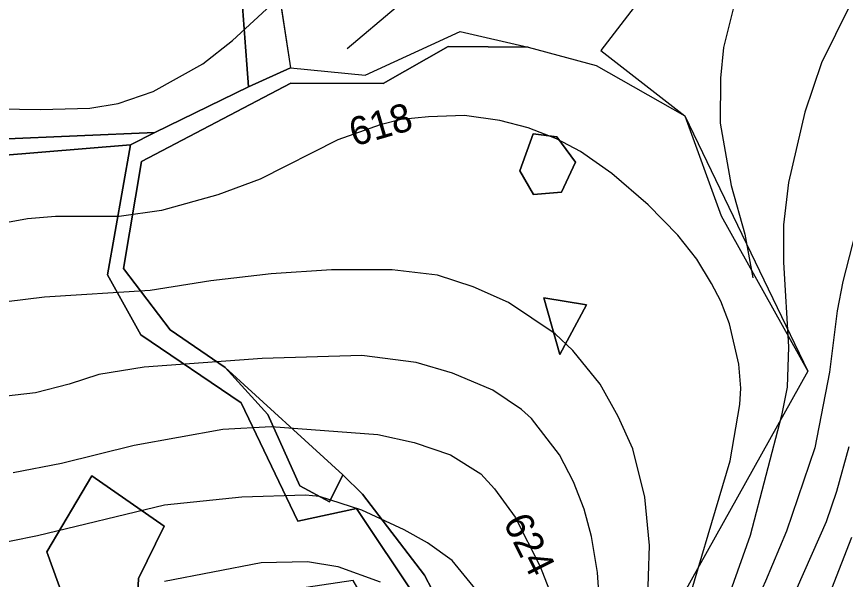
# Model space of a CAD drawing. Extents: x -709418 to -703832, y -1161719 to -1157826.
# Drawn here: x -705715.8 to -705481.3, y -1160126.6 to -1159967.4 of the extents above; entities that cross this region are included whole.
import ezdxf

# ---------------------------------------------------------------- set-up
doc = ezdxf.new("R2010")
doc.units = 0
for name, color, linetype in [('102_obvod PÚ', 7, 'Continuous'), ('120_vrstevnice hlavní', 7, 'Continuous'), ('121_vrstevnice hlavní_popis', 7, 'Continuous'), ('122_vrstevnice základní', 7, 'Continuous'), ('124_vrstevnice doplňková', 7, 'Continuous'), ('206_TTP_KN', 7, 'Continuous'), ('210_ostatní plocha_KN', 7, 'Continuous'), ('609_LBC_stav', 7, 'Continuous')]:
    doc.layers.add(name, color=color, linetype=linetype)

msp = doc.modelspace()

# ---------------------------------------------------------------- linework, layer by layer
at = {"layer": '102_obvod PÚ'}
msp.add_lwpolyline([(-705648.46, -1159916.07), (-705638.24, -1159981.92), (-705617.18, -1159983.99), (-705590.25, -1159971.69), (-705571.02, -1159976.06), (-705551.84, -1159981.31), (-705526.72, -1159995.51), (-705516.48, -1160023.76), (-705491.92, -1160067.67), (-705561.96, -1160193.15), (-705563.65, -1160193.42), (-705572.14, -1160189.71), (-705572.57, -1160180.72), (-705578.63, -1160182.19), (-705583.87, -1160190.33), (-705620.59, -1160126.86), (-705658.56, -1160132.55), (-705655.72, -1160146.23), (-705653.33, -1160157.69), (-705696.03, -1160165.25), (-705691.55, -1160200.19), (-705733.28, -1160203.04)], dxfattribs=at)
at = {"layer": '120_vrstevnice hlavní'}
for points in [[(-705537.29, -1160134.37), (-705536.72, -1160116.99), (-705538.01, -1160103.31), (-705541.43, -1160089.63), (-705545.56, -1160080.51), (-705550.69, -1160071.39), (-705558.38, -1160061.84), (-705563.37, -1160057.14), (-705576.62, -1160048.31), (-705586.6, -1160043.89), (-705596.71, -1160040.61), (-705609.54, -1160039.04), (-705626.64, -1160039.04), (-705643.74, -1160040.18), (-705660.84, -1160042.18), (-705677.93, -1160044.89), (-705707.86, -1160046.74), (-705744.84, -1160051.31)], [(-705479.58, -1160114.71), (-705485.28, -1160129.24), (-705497.54, -1160153.47), (-705506.23, -1160168), (-705512.93, -1160182.54), (-705513.35, -1160187.38), (-705513.22, -1160190.87), (-705511.93, -1160194.22), (-705508.79, -1160196.64), (-705503.81, -1160197.93), (-705501.67, -1160197.93), (-705495.11, -1160194.93), (-705487.28, -1160189.23), (-705470.46, -1160171.99)]]:
    msp.add_lwpolyline(points, dxfattribs=at)
at = {"layer": '122_vrstevnice základní'}
for points in [[(-705726.95, -1159993.45), (-705709, -1159993.73), (-705695.03, -1159993.3), (-705687.05, -1159992.02), (-705677.08, -1159988.6), (-705663.11, -1159980.76), (-705654.71, -1159974.21), (-705636.61, -1159957.4), (-705631.34, -1159950.56), (-705625.92, -1159941.44), (-705621.65, -1159932.32), (-705616.38, -1159918.64), (-705612.67, -1159902.68), (-705611.25, -1159891.28), (-705610.59, -1159877.63), (-705609.82, -1159845.68), (-705607.83, -1159827.44), (-705605.4, -1159816.04), (-705600.13, -1159797.8), (-705596.43, -1159788.68), (-705590.16, -1159777.28), (-705585.17, -1159770.01), (-705578.19, -1159761.75), (-705570.21, -1159755.62)], [(-705460.35, -1159924.34), (-705488.13, -1159980.48), (-705492.83, -1159994.44), (-705497.39, -1160014.39), (-705498.82, -1160026.36), (-705498.82, -1160036.91), (-705497.39, -1160060.85), (-705497.82, -1160072.25), (-705499.39, -1160080.23), (-705508.22, -1160114.14), (-705513.92, -1160130.1)], [(-705528.17, -1160140.93), (-705513.92, -1160093.05), (-705511.22, -1160077.09), (-705510.93, -1160072.53), (-705511.5, -1160065.69), (-705514.07, -1160054.29), (-705516.54, -1160047.92), (-705519.2, -1160042.89), (-705523.33, -1160036.05), (-705528.74, -1160029.21), (-705537.15, -1160020.66), (-705547.41, -1160011.83), (-705556.24, -1160005.56), (-705563.08, -1160002), (-705571.06, -1159998.86), (-705579.04, -1159996.86), (-705589.02, -1159995.44), (-705599.21, -1159995.76), (-705606.97, -1159996.58), (-705612.96, -1159998.01), (-705624.93, -1160002.28), (-705646.87, -1160013.4), (-705658.84, -1160017.81), (-705674.8, -1160022.23), (-705686.77, -1160023.94), (-705704.72, -1160023.94), (-705712.7, -1160024.65), (-705744.62, -1160030.49)], [(-705476.73, -1160021.8), (-705482.08, -1160042.32), (-705483.69, -1160050.67), (-705485.85, -1160067.97), (-705489.93, -1160089.4), (-705498.03, -1160113), (-705503.93, -1160127.1), (-705520.03, -1160162.95), (-705525.32, -1160175.98), (-705537.15, -1160199.92), (-705546.27, -1160215.88), (-705551.97, -1160228.42), (-705553.96, -1160234.4), (-705555.67, -1160242.38), (-705556.24, -1160252.36), (-705554.96, -1160257.2), (-705553.11, -1160259.2), (-705550.97, -1160260.05), (-705544.85, -1160259.06), (-705539, -1160254.21), (-705527.74, -1160241.24), (-705520.91, -1160234.26), (-705494.69, -1160210.61), (-705473.45, -1160189.8)], [(-705550.26, -1160142.64), (-705551.4, -1160124.68), (-705553.11, -1160114.42), (-705555.25, -1160106.73), (-705558.24, -1160099.03), (-705562.23, -1160091.34), (-705570.07, -1160081.08), (-705572.92, -1160078.52), (-705581.04, -1160073.1), (-705592.44, -1160068.26), (-705602.7, -1160065.26), (-705618.09, -1160063.27), (-705646.3, -1160064.12), (-705679.64, -1160066.55), (-705692.47, -1160068.68), (-705700.89, -1160071.37), (-705710.42, -1160073.81), (-705733.51, -1160076.52)], [(-705716.69, -1160096.33), (-705703.01, -1160093.76), (-705682.49, -1160088.63), (-705657.42, -1160084.07), (-705643.74, -1160083.36), (-705613.53, -1160085.64), (-705603.27, -1160087.92), (-705593.01, -1160091.34), (-705584.46, -1160096.75), (-705580.61, -1160101.03), (-705574.77, -1160109.01), (-705567.64, -1160122.97), (-705564.51, -1160130.95)], [(-705478.3, -1160187.67), (-705494.97, -1160202.91), (-705518.06, -1160222.29), (-705522.47, -1160224.71), (-705526.6, -1160225.71), (-705529.46, -1160225.43), (-705531.05, -1160225.11), (-705532.88, -1160223.72), (-705534.87, -1160220.72), (-705535.31, -1160218.34), (-705534.87, -1160217.16), (-705531.71, -1160208.42), (-705523.61, -1160195.07), (-705521.33, -1160189.09), (-705517.06, -1160173.99), (-705513.07, -1160164.01), (-705494.97, -1160128.96), (-705486.71, -1160110.25), (-705483.71, -1160101.6), (-705480.3, -1160089.06)], [(-705583.18, -1160132.66), (-705592.58, -1160121.26), (-705599.56, -1160116.28), (-705606.12, -1160112.57), (-705618.09, -1160107.01), (-705630.06, -1160103.17), (-705634.05, -1160102.74), (-705652, -1160103.31), (-705673.94, -1160105.59), (-705709.85, -1160114.28), (-705724.81, -1160117.27)], [(-705673.94, -1160127.1), (-705646.59, -1160121.83), (-705633.48, -1160121.55), (-705624.93, -1160122.97), (-705612.96, -1160127.25)]]:
    msp.add_lwpolyline(points, dxfattribs=at)
at = {"layer": '124_vrstevnice doplňková'}
for points in [[(-705622.23, -1159976.45), (-705608.4, -1159964.81), (-705591.16, -1159947.42), (-705586.04, -1159940.46), (-705584.23, -1159936.82), (-705582.81, -1159932.81), (-705581.47, -1159926.33), (-705580.9, -1159921.2), (-705581.04, -1159916.36), (-705582.18, -1159911.23), (-705589.16, -1159894.13), (-705595.29, -1159882.16), (-705597.14, -1159876.88), (-705597.92, -1159873.24)], [(-705512.64, -1159963.38), (-705515.78, -1159976.2), (-705516.63, -1159984.9), (-705516.77, -1159997.58), (-705513.64, -1160015.25), (-705509.79, -1160028.93), (-705507.51, -1160041.32)]]:
    msp.add_lwpolyline(points, dxfattribs=at)
at = {"layer": '206_TTP_KN'}
for p, q in [((-705738.1, -1160008.15), (-705683.57, -1160003.75)), ((-705683.57, -1160003.75), (-705690.01, -1160040.49)), ((-705690.01, -1160040.49), (-705680.6, -1160057.4)), ((-705680.6, -1160057.4), (-705652.2, -1160076.63)), ((-705652.2, -1160076.63), (-705636.24, -1160110.11)), ((-705694.5, -1160097.28), (-705707.2, -1160118.77)), ((-705673.98, -1160111.51), (-705694.5, -1160097.28)), ((-705636.24, -1160110.11), (-705619.61, -1160106.54)), ((-705619.61, -1160106.54), (-705598.52, -1160138.1)), ((-705681.23, -1160126.34), (-705673.98, -1160111.51)), ((-705707.2, -1160118.77), (-705698.8, -1160141.8)), ((-705682.04, -1160139.32), (-705681.23, -1160126.34))]:
    msp.add_line(p, q, dxfattribs=at)
for points in [[(-705724.76, -1159911.44), (-705707.95, -1159909.6), (-705690.06, -1159913.5), (-705674.28, -1159911.37), (-705666.92, -1159916.15), (-705655.7, -1159912.96), (-705650.12, -1159987.35), (-705676.69, -1160000.18), (-705720.68, -1160002.07)], [(-705685.56, -1160038.68), (-705680.46, -1160008.39), (-705638.14, -1159986.31), (-705612.09, -1159986.38), (-705593.69, -1159975.9), (-705571.02, -1159976.06), (-705551.84, -1159981.31), (-705526.72, -1159995.51), (-705516.48, -1160023.76), (-705491.92, -1160067.67), (-705561.96, -1160193.15), (-705563.65, -1160193.42), (-705572.14, -1160189.71), (-705572.57, -1160180.72), (-705571.96, -1160179.56), (-705574.58, -1160174.6), (-705600.41, -1160125.42), (-705617.9, -1160102.48), (-705623.47, -1160096.98), (-705656.75, -1160066.64), (-705672.32, -1160056.02), (-705685.56, -1160038.68)], [(-705573.41, -1160011.05), (-705569.58, -1160017.77), (-705561.66, -1160017.13), (-705557.62, -1160008.64), (-705562.93, -1160001.49), (-705569.65, -1160000.57), (-705573.41, -1160011.05)], [(-705566.61, -1160046.93), (-705562.08, -1160063), (-705554.51, -1160048.98), (-705566.61, -1160046.93)]]:
    msp.add_lwpolyline(points, dxfattribs=at)
at = {"layer": '210_ostatní plocha_KN'}
for p, q in [((-705650.12, -1159987.35), (-705655.7, -1159912.96)), ((-705648.46, -1159916.07), (-705638.24, -1159981.92)), ((-705617.18, -1159983.99), (-705590.25, -1159971.69)), ((-705590.25, -1159971.69), (-705571.02, -1159976.06)), ((-705593.69, -1159975.9), (-705612.09, -1159986.38)), ((-705571.02, -1159976.06), (-705593.69, -1159975.9)), ((-705650.12, -1159987.35), (-705638.24, -1159981.92)), ((-705638.24, -1159981.92), (-705650.12, -1159987.35)), ((-705638.24, -1159981.92), (-705617.18, -1159983.99)), ((-705638.14, -1159986.31), (-705680.46, -1160008.39)), ((-705612.09, -1159986.38), (-705638.14, -1159986.31)), ((-705676.69, -1160000.18), (-705650.12, -1159987.35)), ((-705720.68, -1160002.07), (-705676.69, -1160000.18)), ((-705676.69, -1160000.18), (-705683.57, -1160003.75)), ((-705683.57, -1160003.75), (-705676.69, -1160000.18)), ((-705573.41, -1160011.05), (-705569.65, -1160000.57)), ((-705569.65, -1160000.57), (-705562.93, -1160001.49)), ((-705562.93, -1160001.49), (-705557.62, -1160008.64)), ((-705683.57, -1160003.75), (-705738.1, -1160008.15)), ((-705690.01, -1160040.49), (-705683.57, -1160003.75)), ((-705680.46, -1160008.39), (-705685.56, -1160038.68)), ((-705557.62, -1160008.64), (-705561.66, -1160017.13)), ((-705569.58, -1160017.77), (-705573.41, -1160011.05)), ((-705561.66, -1160017.13), (-705569.58, -1160017.77)), ((-705680.6, -1160057.4), (-705690.01, -1160040.49)), ((-705685.56, -1160038.68), (-705672.32, -1160056.02)), ((-705566.61, -1160046.93), (-705554.51, -1160048.98)), ((-705562.08, -1160063), (-705566.61, -1160046.93)), ((-705554.51, -1160048.98), (-705562.08, -1160063)), ((-705672.32, -1160056.02), (-705656.75, -1160066.64)), ((-705652.2, -1160076.63), (-705680.6, -1160057.4)), ((-705656.75, -1160066.64), (-705644.65, -1160079.94)), ((-705656.75, -1160066.64), (-705623.47, -1160096.98)), ((-705644.65, -1160079.94), (-705656.75, -1160066.64)), ((-705636.24, -1160110.11), (-705652.2, -1160076.63)), ((-705644.65, -1160079.94), (-705635.66, -1160100.11)), ((-705635.66, -1160100.11), (-705644.65, -1160079.94)), ((-705707.2, -1160118.77), (-705694.5, -1160097.28)), ((-705694.5, -1160097.28), (-705673.98, -1160111.51)), ((-705627.24, -1160104.64), (-705623.47, -1160096.98)), ((-705623.47, -1160096.98), (-705627.24, -1160104.64)), ((-705623.47, -1160096.98), (-705617.9, -1160102.48)), ((-705635.66, -1160100.11), (-705627.24, -1160104.64)), ((-705627.24, -1160104.64), (-705635.66, -1160100.11)), ((-705617.9, -1160102.48), (-705600.41, -1160125.42)), ((-705619.61, -1160106.54), (-705636.24, -1160110.11)), ((-705598.52, -1160138.1), (-705619.61, -1160106.54)), ((-705673.98, -1160111.51), (-705681.23, -1160126.34)), ((-705698.8, -1160141.8), (-705707.2, -1160118.77)), ((-705681.23, -1160126.34), (-705682.04, -1160139.32)), ((-705600.41, -1160125.42), (-705574.58, -1160174.6))]:
    msp.add_line(p, q, dxfattribs=at)
at = {"layer": '609_LBC_stav'}
msp.add_lwpolyline([(-705517, -1160362.3), (-705369.22, -1160210.37), (-705299.31, -1160130.26), (-705201.9, -1160128.94), (-705159.78, -1160035.52), (-705055.56, -1159909.96), (-705073.99, -1159896.8), (-705110.85, -1159883.64), (-705179.3, -1159879.69), (-705206.94, -1159849.43), (-705259.6, -1159815.22), (-705278.03, -1159792.85), (-705321.47, -1159804.69), (-705388.6, -1159766.54), (-705550.51, -1159977.06), (-705526.72, -1159995.51), (-705491.92, -1160067.67), (-705561.96, -1160193.15), (-705583.87, -1160190.33), (-705632.13, -1160220.48), (-705677.11, -1160208.39), (-705689.77, -1160240.43), (-705690.96, -1160281.19), (-705760.43, -1160283.48)], dxfattribs=at)

# ---------------------------------------------------------------- texts
at = {"layer": '121_vrstevnice hlavní_popis'}
for s, rotation, p in [('618', 16.1201, (-705620.29, -1160004.23)), ('624', 296.6662, (-705578.26, -1160110.44))]:
    msp.add_text(s, height=8, rotation=rotation, dxfattribs=at).set_placement(p)

doc.saveas('drawing.dxf')
